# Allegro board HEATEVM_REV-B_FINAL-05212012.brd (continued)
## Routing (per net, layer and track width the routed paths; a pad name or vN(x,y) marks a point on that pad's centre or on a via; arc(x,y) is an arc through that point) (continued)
ADSCLK: length 36.7
  TOP w0.254: v1(261.62,15.88) 261.41,16.08 U4.38
  TOP w0.305: SB31.2 JP16.5
  L5_SIG w0.305: JP16.5 285.31,20.19 265.18,20.19 261.62,16.64 v1(261.62,15.88)
ADSYNC: length 38
  TOP w0.254: v1(258.19,16.38) 258.39,16.58 U4.39
  TOP w0.305: SB33.2 JP16.1
  L5_SIG w0.305: JP16.1 288.8,20.76 288.61,20.95 265.05,20.95 260.48,16.38 v1(258.19,16.38)
AMP_OUT_CH1_P02: length 14
  TOP w0.305: v1(27.3,4.45) 27.43,4.57 U1.6
  BOTTOM w0.305: v1(27.3,4.45) 26.92,4.06 R15.1 R92.2 26.16,6.86 25.91,7.11 C17.2
AMP_OUT_CH2_P02: length 14
  TOP w0.305: U2.6 27.43,13.72 v1(27.3,13.59)
  BOTTOM w0.305: C24.2 25.91,16.26 26.16,16 R94.2 R31.1 26.92,13.21 v1(27.3,13.59)
AMP_OUT_CH3_P02: length 14
  TOP w0.305: v1(27.3,22.73) 27.43,22.86 U3.6
  BOTTOM w0.305: v1(27.3,22.73) 26.92,22.35 R35.1 R97.2 26.16,25.15 25.91,25.4 C32.2
AMP_VCOM_CH5_P02: length 7.8
  TOP w0.635: JP9.1 43.69,2.08 SB5.2 ; U8.2 49.91,18.03
  TOP w0.889: 49.91,18.03 49.15,18.8 v1(47.12,18.8)
  vias: v1(47.12,18.03) v1(47.12,17.27)
AMP_VCOM_CH8_P03: length 7.8
  TOP w0.635: SB6.2 64.26,2.08 JP502.1 ; U14.2 89.53,18.03
  TOP w0.889: v1(86.74,18.8) 88.77,18.8 89.53,18.03
  vias: v1(86.74,18.03) v1(86.74,17.27)
AWD_P05: length 25.5
  TOP w0.254: U19.21 v1(320.68,8.08)
  TOP w0.305: TP2.1 312.55,16.89 v1(309.75,16.89)
  L5_SIG w0.305: v1(320.68,8.08) 319.83,7.24 313.31,7.24 312.17,8.38 312.17,13.21 309.75,15.62 v1(309.75,16.89)
  BOTTOM w0.305: R85.2 v1(320.68,8.08)
BRDGM_P03: length 18.2
  TOP w0.305: U11.5 v1(77.34,18.16)
  L5_SIG w0.305: JP8.2 75.69,19.81 v1(77.34,18.16)
BRDGP_P03: length 19.5
  TOP w0.305: U11.3 v1(78.61,24)
  L5_SIG w0.305: JP8.3 76.96,22.35 v1(78.61,24)
BUF-BRDGM_P03: length 14.1
  TOP w0.305: U11.7 79.88,17.61 79.59,17.91 v1(79.25,17.91) 78.87,17.91 78.61,17.65 U11.6
  L5_SIG w0.305: v1(79.25,17.91) 81.66,20.32 v1(86.87,20.32)
  BOTTOM w0.305: R55.1 v1(86.87,20.32)
BUF-BRDGP_P03: length 12.9
  TOP w0.305: U11.1 81.15,24.51 80.9,24.26 v1(80.52,24.26) 80.18,24.26 79.88,24.55 U11.2
  L5_SIG w0.305: v1(80.52,24.26) 82.93,21.84 v1(86.87,21.84)
  BOTTOM w0.305: R53.2 v1(86.87,21.84)
CANH1_P05: length 10.6
  TOP w0.305: v1(393.19,17.4) 393.32,17.53 U17.7
  BOTTOM w0.305: JP22.1 392.68,25.27 392.94,25.02 R79.2 392.94,18.41 393.19,18.16 v1(393.19,17.4)
CANH2_P05: length 11.3
  TOP w0.305: U16.7 v1(384.18,17.4)
  BOTTOM w0.305: v1(384.18,17.4) 384.18,19.81 382.02,21.97 R78.2 382.02,25.02 381.76,25.27 JP23.1
CANL1_P05: length 10.6
  TOP w0.305: v1(394.72,17.4) 394.72,17.53 394.59,17.65 U17.6
  BOTTOM w0.305: JP22.2 395.22,25.27 394.97,25.02 R79.1 394.97,18.41 394.72,18.16 v1(394.72,17.4)
CANL2_P05: length 11
  TOP w0.305: U16.6 v1(385.44,17.4)
  BOTTOM w0.305: v1(385.44,17.4) 385.44,20.45 384.05,21.84 R78.1 384.05,25.02 384.3,25.27 JP23.2
CANRX_1_P05: length 79.1
  TOP w0.254: U19.49 v1(339.73,11.08)
  TOP w0.305: U17.4 v1(395.86,11.3)
  L4_SIG w0.305: v1(395.86,11.3) 395.86,12.7 393.07,15.49 381.25,15.49 380.87,15.11 368.94,15.11 359.03,25.02 343.66,25.02 340.49,21.84 340.49,13.59 339.73,12.83 v1(339.73,11.08)
CANRX_2_P05: length 75.1
  TOP w0.254: v1(326.16,1.65) 326.16,2.54 326.41,2.79 U19.29
  TOP w0.305: U16.4 v1(386.71,11.3)
  L4_SIG w0.305: v1(326.16,1.65) 326.16,2.82 327.15,3.81 335.41,3.81 337.69,1.52 376.68,1.52 381,5.84 381,10.92 382.27,12.19 385.83,12.19 v1(386.71,11.3)
CANTX_1_P05: length 71.7
  TOP w0.254: U19.50 338.99,11.58 339.22,11.81 v1(340.87,11.81)
  TOP w0.305: 392.05,9.65 v1(392.05,11.3)
  L4_SIG w0.305: v1(340.87,11.81) 341.32,12.26 341.32,20.64 343.15,22.48 358.9,22.48 366.9,14.48 381.76,14.48 382.14,14.86 389.38,14.86 392.05,12.19 v1(392.05,11.3)
CANTX_2_P05: length 68.6
  TOP w0.254: U19.30 v1(326.91,2.29)
  TOP w0.305: 382.9,9.65 v1(382.9,11.3)
  L4_SIG w0.305: v1(382.9,11.3) 382.9,4.06 379.73,0.89 337.19,0.89 336.3,1.78 328.55,1.78 328.04,2.29 v1(326.91,2.29)
CLKDIV_P04: length 18.4
  TOP w0.254: U4.15 v1(252.95,2.41)
  TOP w0.635: SB21.2 262.64,2.08 JP13.1
  BOTTOM w0.305: R62.1 JP13.1 262.64,2.79 261.49,1.65 253.71,1.65 v1(252.95,2.41)
CLKOUT_P05: length 31.7
  TOP w0.362: U19.48 335.53,10.58 v1(334.73,9.78) ; JP1.3 313.94,2.08 SB23.2
  BOTTOM w0.362: v1(334.73,9.78) 334.73,5.42 333.5,4.19 323.34,4.19 322.33,3.17 315.62,3.17 314.99,3.81 JP1.3
D6M_P03: length 10
  TOP w0.305: 83.31,10.29 v1(84.96,10.29)
  L4_SIG w0.305: JP26.5 83.57,8.89 v1(84.96,10.29)
D6P_P03: length 9.1
  TOP w0.305: U12.3 v1(81.53,9.02)
  L4_SIG w0.305: JP26.6 80.31,3.26 80.31,7.79 v1(81.53,9.02)
D7M_P03: length 24.7
  L4_SIG w0.305: JP26.1 93.73,3.98 96.39,6.64 96.39,13.97 102.74,20.32 v1(104.65,20.32)
  BOTTOM w0.305: R52.2 v1(104.65,20.32)
D7P_P03: length 27.3
  L4_SIG w0.305: JP26.2 91.19,4.19 92.84,5.84 92.84,12.06 102.62,21.84 v1(104.65,21.84)
  BOTTOM w0.305: R48.2 v1(104.65,21.84)
D7PDN_P03: length 40.6
  TOP w0.305: C507.1 v1(98.89,22.14) ; v1(104.65,23.37) 106.55,23.37 107.31,24.13 U13.7
  L4_SIG w0.305: JP26.4 86.11,5.08 87.76,6.73 87.76,14.73 95.16,22.14 v1(98.89,22.14)
  BOTTOM w0.305: v1(104.65,23.37) 103.42,22.14 v1(98.89,22.14)
D485_A_P05: length 20.4
  TOP w0.305: U15.6 376.3,17.78 376.43,17.65 v1(376.43,15.88)
  L5_SIG w0.305: JP18.2 367.03,23.75 370.84,23.75 376.43,18.16 v1(376.43,15.88)
D485_B_P05: length 20.8
  TOP w0.305: v1(374.9,15.88) 374.9,17.65 375.03,17.78 U15.7
  L5_SIG w0.305: JP18.1 365.63,22.61 369.44,22.61 374.9,17.14 v1(374.9,15.88)
D-BRDGM_P03: length 6.4
  TOP w0.305: U14.1 v1(87.38,16.25)
  BOTTOM w0.305: v1(87.38,16.25) 88.39,16.25 ; 88.39,16.25 88.14,16.51 R55.2 R56.2 ; 88.39,16.25 C11.1
D-BRDGP_P03: length 6.4
  TOP w0.305: U14.8 v1(87.38,25.91)
  BOTTOM w0.305: R54.2 R53.1 88.14,25.65 88.39,25.91 ; 88.39,25.91 C48.1 ; 88.39,25.91 v1(87.38,25.91)
D-RTDM_P02: length 11.6
  TOP w0.305: R21.1 43.05,18.54 45.34,16.25 v1(47.75,16.25) U8.1
  BOTTOM w0.305: v1(47.75,16.25) 48.58,16.25 C18.1 49.53,16.32 R20.2
D-RTDP_P02: length 11.7
  TOP w0.305: U8.8 v1(47.75,25.91) 45.34,25.91 43.05,23.62 R18.1
  BOTTOM w0.305: R19.2 49.53,25.91 C20.1 48.52,25.91 v1(47.75,25.91)
DIN: length 48
  TOP w0.254: v1(254.25,5.84) 253.95,5.54 U4.17
  TOP w0.305: SB34.2 JP16.7
  L4_SIG w0.305: v1(254.25,5.84) 255.02,6.6 257.43,6.6 258.7,5.33 264.54,5.33 265.81,4.06 285.62,4.06 287.27,5.71 287.27,10.6 JP16.7
DOUT1: length 41.3
  TOP w0.254: U4.25 v1(261.62,9.58)
  TOP w0.305: SB35.2 JP16.9
  L5_SIG w0.305: JP16.9 285.96,10.6 284.93,9.58 ; 284.93,9.58 286.13,8.38 286.13,3.68 JP7.1 ; 284.93,9.58 284.48,10.03 262.07,10.03 v1(261.62,9.58)
DOUT2_P04: length 36.1
  TOP w0.254: U4.24 v1(258.19,9.08)
  L5_SIG w0.305: v1(258.19,9.08) 259.59,9.08 259.91,8.76 262,8.76 262.51,9.27 283.97,9.27 285.12,8.13 285.12,5.21 JP7.2
DOUT3_P04: length 32.6
  TOP w0.254: U4.23 261.29,8.58 261.62,8.26 v1(261.62,8)
  L5_SIG w0.305: v1(261.62,8) 262.51,8 263.14,8.64 282.83,8.64 284.23,7.24 284.23,5.84 282.83,4.45 281.81,4.45 JP7.3
DOUT4_P04: length 23.2
  TOP w0.254: U4.22 v1(258.19,8.08)
  L5_SIG w0.305: JP7.4 273.18,6.73 261.37,6.73 260.02,8.08 v1(258.19,8.08)
DOUT5_P04: length 21.8
  TOP w0.254: U4.21 255.95,5.54 256.26,5.84 v1(256.29,5.84)
  L5_SIG w0.305: JP7.5 271.53,5.84 v1(256.29,5.84)
DOUT6_P04: length 20.2
  TOP w0.254: v1(255.27,5.84) 255.45,5.66 U4.20
  L5_SIG w0.305: v1(255.27,5.84) 256.03,5.08 269.75,5.08 JP7.6
DOUT7_P04: length 17.4
  TOP w0.254: U4.19 254.95,2.73 v1(255.27,2.41)
  L5_SIG w0.305: JP7.7 268.48,3.81 265.94,3.81 264.54,2.41 v1(255.27,2.41)
DOUT8_P04: length 15.7
  TOP w0.254: v1(254.13,2.41) 254.45,2.74 U4.18
  L5_SIG w0.305: JP7.8 266.19,1.52 255.02,1.52 v1(254.13,2.41)
FLCLK_P05: length 91.5
  TOP w0.362: SB23.1 311.4,2.08 ; 311.4,2.08 JP1.2 ; 311.4,2.08 SB24.1 ; v1(392.05,4.95) 392.21,5.12 U18.5
  BOTTOM w0.362: JP1.2 313.06,2.16 322.58,2.16 323.72,3.3 335.79,3.3 337.95,1.14 386.84,1.14 390.65,4.95 v1(392.05,4.95)
FORMAT0_P04: length 24.9
  TOP w0.254: U4.42 v1(259.91,19.05)
  TOP w0.305: SB17.2 JP10.1
  L5_SIG w0.305: JP10.1 275.63,23.16 263,23.16 259.91,20.07 v1(259.91,19.05)
  BOTTOM w0.305: R5.2 JP10.1
FORMAT1_P04: length 28.4
  TOP w0.254: U4.41 261.24,17.58 261.62,17.96 261.62,18.41 v1(260.99,19.05)
  TOP w0.305: SB18.2 JP10.3
  L5_SIG w0.305: v1(260.99,19.05) 260.99,19.68 263.78,22.48 277.5,22.48 JP10.3
  BOTTOM w0.305: R4.2 JP10.3
FORMAT2_P04: length 32.6
  TOP w0.254: U4.40 258.64,17.08 v1(258.19,17.53)
  TOP w0.305: SB19.2 JP10.5
  L5_SIG w0.305: v1(258.19,17.53) 260.6,17.53 264.8,21.72 279.27,21.72 JP10.5
  BOTTOM w0.305: R3.2 JP10.5
GPIOA0_P05: length 4.6
  TOP w0.254: U19.83 323.41,23.8 323.34,23.88 v1(323.34,24)
  L4_SIG w0.305: JP14.1 323.34,25.53 v1(323.34,24)
GPIOA1_P05: length 60.6
  TOP w0.254: U19.80 324.91,23.37 324.36,23.92 v1(324.36,24)
  TOP w0.305: SB36.1 286.31,7.38 286.89,6.79 291.08,6.79 JP16.12
  L4_SIG w0.305: JP14.2 324.36,25.53 v1(324.36,24) 324.36,23.37 323.34,22.35 323.34,8.89 320.8,6.35 298.2,6.35 296.48,8.06 JP16.12
GPIOA2_P05: length 5.5
  TOP w0.254: U19.79 v1(325.41,24)
  L4_SIG w0.305: JP14.3 326.94,25.57 326.35,25.57 325.41,24.64 v1(325.41,24)
GPIOA3_P05: length 7.1
  TOP w0.254: v1(326.39,24) 326.39,23.88 325.91,23.4 U19.78
  L4_SIG w0.305: JP14.4 329.5,25.59 328.74,25.59 328.17,25.02 327.15,25.02 326.39,24.26 v1(326.39,24)
GPIOA4_P05: length 7.4
  TOP w0.254: U19.73 v1(328.41,24.26)
  L4_SIG w0.305: JP14.5 331.28,24.83 328.99,24.83 328.87,24.71 328.86,24.71 v1(328.41,24.26)
GPIOA5_P05: length 12.4
  TOP w0.254: U19.58 335.47,15.58 335.03,16.03 v1(335.03,17.27)
  L4_SIG w0.305: JP14.6 335.28,19.05 335.03,18.8 v1(335.03,17.27)
GPIOA6_P05: length 20.6
  TOP w0.254: U19.46 v1(338.96,9.58)
  L4_SIG w0.305: v1(338.96,9.58) 338.33,9.58 336.68,11.23 336.68,24 337.82,25.15 JP14.7
GPIOA7_P05: length 23.6
  TOP w0.254: U19.47 338.33,10.08 338.6,10.35 340.55,10.35 v1(340.87,10.67)
  L4_SIG w0.305: v1(340.87,10.67) 340.42,10.22 339.41,10.22 337.95,11.68 337.95,16.89 338.71,17.65 338.71,23.62 340.36,25.27 JP14.8
HET2_P05: length 43.8
  TOP w0.254: v1(332.23,2.41) 332.41,2.59 U19.41
  L5_SIG w0.305: v1(332.23,2.41) 332.23,3.17 330.96,4.45 323.98,4.45 321.69,6.73 321.69,9.27 319.91,11.05 314.45,11.05 313.12,12.38 313.12,13.4 310.83,15.68 310.83,18.99 306.07,23.75 JP15.3
HET3_P05: length 45.8
  TOP w0.254: U19.38 330.91,2.72 v1(331.22,2.41)
  L5_SIG w0.305: v1(331.22,2.41) 331.22,3.05 330.45,3.81 321.44,3.81 318.64,6.6 312.93,6.6 311.4,8.13 311.4,12.95 308.86,15.49 308.86,19.43 303.53,24.77 JP15.2
HET4_P05: length 46
  TOP w0.254: U19.37 330.41,2.63 v1(330.2,2.41)
  L5_SIG w0.305: JP15.1 300.99,25.15 308.1,18.03 308.1,15.11 310.64,12.57 310.64,7.87 312.55,5.97 316.87,5.97 319.66,3.17 329.44,3.17 v1(330.2,2.41)
HET6_P05: length 14
  TOP w0.254: U19.6 317.26,15.58 317.09,15.75 v1(316.48,15.75)
  L5_SIG w0.305: JP15.8 318.77,18.03 v1(316.48,15.75)
HET8_P05: length 15
  TOP w0.254: v1(316.48,14.73) 317.09,14.73 317.44,15.08 U19.7
  L5_SIG w0.305: JP15.7 316.23,18.16 315.6,17.53 315.6,15.24 316.1,14.73 v1(316.48,14.73)
HOLDN_P05: length 4.4
  TOP w0.305: v1(397.38,2.29) 396.95,2.72 U18.2
  BOTTOM w0.305: v1(397.38,2.29) 396.62,1.52 R99.1
I-ADC_CH5M_P02: length 6.7
  TOP w0.305: v1(53.34,16.26) 53.21,16.26 53.21,16.25 U8.4
  BOTTOM w0.305: R501.2 R20.1 51.56,16.32 C18.2 52.51,16.26 v1(53.34,16.26)
I-ADC_CH5P_P02: length 6.8
  TOP w0.305: v1(53.34,25.91) 53.34,25.91 U8.5
  BOTTOM w0.305: v1(53.34,25.91) 52.58,25.91 C20.2 51.56,25.91 R19.1 R502.2
I-ADC_CH7M_P03: length 4.4
  TOP w0.305: v1(110.74,25.91) U13.5
  BOTTOM w0.305: v1(110.74,25.91) 109.73,25.91 ; 109.73,25.91 C56.2 ; 109.73,25.91 109.98,25.65 R49.2
I-ADC_CH7P_P03: length 4.4
  TOP w0.305: U13.4 v1(110.74,16.25)
  BOTTOM w0.305: 109.73,16.25 109.98,16.51 R50.2 ; 109.73,16.25 C58.2 ; 109.73,16.25 v1(110.74,16.25)
I-ADC_CH8M_P03: length 4.4
  TOP w0.305: U14.4 v1(92.96,16.25)
  BOTTOM w0.305: 91.95,16.25 92.2,16.51 R58.2 ; 91.95,16.25 v1(92.96,16.25) ; 91.95,16.25 C11.2
I-ADC_CH8P_P03: length 4.4
  TOP w0.305: v1(92.96,25.91) U14.5
  BOTTOM w0.305: 91.95,25.91 C48.2 ; 91.95,25.91 v1(92.96,25.91) ; 91.95,25.91 92.2,25.65 R57.2
I_INM_4_P03: length 27.6
  TOP w0.305: v1(58.29,10.67) R37.2
  L4_SIG w0.305: JP26.7 74.8,6.22 74.8,9.4 72.64,11.56 59.18,11.56 v1(58.29,10.67)
I_INP_1_P02: length 4.1
  BOTTOM w0.305: R30.1 R13.2 C17.1
I_INP_2_P02: length 4.1
  BOTTOM w0.305: R44.1 R29.2 C24.1
I_INP_3_P02: length 4.1
  BOTTOM w0.305: C32.1 R34.2 R46.1
INM_1_P02: length 4.9
  TOP w0.305: U1.2 v1(20.95,5.84)
  BOTTOM w0.305: v1(20.95,5.84) 21.21,6.1 R93.2 R92.1
INM_2_P02: length 4.9
  TOP w0.305: U2.2 v1(20.95,14.99)
  BOTTOM w0.305: v1(20.95,14.99) 21.21,15.24 R95.2 R94.1
INM_3_P02: length 4.9
  TOP w0.305: U3.2 v1(20.95,24.13)
  BOTTOM w0.305: v1(20.95,24.13) 21.21,24.38 R96.2 R97.1
INM_4_P03: length 9.3
  TOP w0.305: R37.1 62.51,10.67 62.89,10.29 v1(66.67,10.29)
  BOTTOM w0.305: v1(66.67,10.29) 67.44,10.29 C45.1 68.58,11.43 R38.1
INM_7_P03: length 6.4
  TOP w0.305: U13.1 v1(105.16,16.25)
  BOTTOM w0.305: 106.17,16.25 C58.1 ; 106.17,16.25 v1(105.16,16.25) ; 106.17,16.25 105.92,16.51 R52.1 R51.2
INP_1_P02: length 6.2
  TOP w0.305: v1(17.53,4.57) U1.3
  BOTTOM w0.305: C37.1 19.15,1.78 18.74,2.19 18.74,2.22 18.03,2.92 R30.2 18.03,4.06 v1(17.53,4.57)
INP_2_P02: length 6.2
  TOP w0.305: v1(17.53,13.72) U2.3
  BOTTOM w0.305: C33.1 19.15,10.92 18.74,11.33 18.74,11.36 18.03,12.06 R44.2 18.03,13.21 v1(17.53,13.72)
INP_3_P02: length 6.2
  TOP w0.305: v1(17.53,22.86) U3.3
  BOTTOM w0.305: C30.1 19.15,20.07 18.74,20.48 18.74,20.5 18.03,21.21 R46.2 18.03,22.35 v1(17.53,22.86)
INP_4_P03: length 9.3
  TOP w0.305: v1(66.67,9.02) U9.3 62.89,9.02 62.51,8.64 R39.2
  BOTTOM w0.305: R40.1 68.58,7.87 C50.1 67.44,9.02 v1(66.67,9.02)
INP_7_P03: length 6.4
  TOP w0.305: U13.8 v1(105.16,25.91)
  BOTTOM w0.305: 106.17,25.91 105.92,25.65 R48.1 R47.2 ; 106.17,25.91 C56.1 ; 106.17,25.91 v1(105.16,25.91)
INT_2P5VREF_P02: length 8
  TOP w0.635: SB3.2 132.59,2.08 JP5.1 ; 122.05,13.97 v1(121.28,13.21) ; 122.05,13.97 v1(122.81,13.21) ; 122.05,13.97 U6.6
IO_CTRL_P05: length 30.9
  TOP w0.305: U15.2 v1(375.03,11.94) 375.79,11.94 376.3,11.43 U15.3
  BOTTOM w0.305: JP17.2 374.9,27.3 376.56,27.3 380.24,23.62 R64.1 375.92,12.83 v1(375.03,11.94)
ISO_VREF_P02: length 7.1
  TOP w0.305: U7.7 49.02,11.05 48.39,10.41 v1(48.39,9.78) U7.6
  BOTTOM w0.305: R25.2 v1(48.39,9.78)
JTCK_P05: length 48.3
  TOP w0.254: U19.45 338.33,9.08 338.52,8.89 339.62,8.89 339.75,8.76 v1(340.36,8.76)
  TOP w0.635: SB25.1 340.87,2.08 JP21.2
  L4_SIG w0.305: v1(340.36,8.76) 341.63,8.76 343.03,10.16 343.03,15.24 343.92,16.13 JP20.9
  BOTTOM w0.305: JP21.2 341.76,4.7 351.03,4.7 351.28,4.95 R65.2 353.06,5.97 354.33,7.24 354.33,11.68 353.69,12.32 350.65,12.32 348.11,14.86 346.2,14.86 JP20.9
JTDI_P05: length 36.1
  TOP w0.254: v1(338.84,7.49) 338.71,7.62 338.28,7.62 337.82,8.08 U19.43
  L4_SIG w0.305: 344.93,21.21 342.26,18.54 342.26,10.67 341.12,9.53 339.85,9.53 338.84,8.51 v1(338.84,7.49)
  L5_SIG w0.305: 344.93,21.21 345.95,22.23 351.92,22.23 354.46,19.68 354.46,17.53 JP19.3
  BOTTOM w0.305: R68.1 JP19.3
JTDO_P05: length 18.9
  TOP w0.254: U19.44 338.2,8.58 338.35,8.43 339.29,8.43 v1(339.73,8)
  L4_SIG w0.305: v1(339.73,8) 342.14,8 344.21,10.08 344.21,10.33 346.2,12.32 351.79,12.32 JP19.7
JTMS2_P05: length 4.3
  TOP w0.254: U19.10 320.41,13.58 v1(320.68,13.84)
  BOTTOM w0.305: v1(320.68,13.84) 319.53,14.99 319.53,15.88
JTMS_P05: length 39.5
  TOP w0.254: v1(320.68,12.83) 320.55,12.83 320.29,13.08 U19.11
  L5_SIG w0.305: v1(320.68,12.83) 326.14,18.29 339.09,18.29 339.47,18.67 JP20.7 346.2,19.94 351.79,19.94 JP19.1
  BOTTOM w0.305: R67.1 JP19.1
JTRSTN_P05: length 46.6
  TOP w0.254: U19.84 322.91,22.99 322.2,23.7 v1(322.2,24)
  L5_SIG w0.305: v1(322.2,24) 322.2,24.38 322.83,25.02 343.66,25.02 344.93,23.75 346.46,25.27 350.77,25.27 355.6,20.45 JP19.2
  BOTTOM w0.305: JP19.2 353.06,21.21 R69.2
LBK1_P05: length 10.4
  TOP w0.305: v1(395.73,17.4) 395.86,17.53 U17.5 ; v1(398.65,19.3) TP3.1
  L4_SIG w0.305: v1(395.73,17.4) 395.73,18.03 397,19.3 v1(398.65,19.3)
  BOTTOM w0.305: R72.2 395.86,17.27 v1(395.73,17.4)
LBK2_P05: length 20.8
  TOP w0.305: U16.5 v1(386.71,17.4) ; TP4.1 v1(398.65,14.48)
  L4_SIG w0.305: v1(386.71,17.4) 387.86,18.54 393.32,18.54 393.95,17.91 393.95,17.02 395.35,15.62 397.51,15.62 v1(398.65,14.48)
  BOTTOM w0.305: v1(386.71,17.4) R74.2
MCS_P05: length 25.6
  TOP w0.305: SB26.2 JP27.2 ; v1(376.3,3.52) U18.12
  L5_SIG w0.305: JP27.2 369.95,13.59 376.3,7.24 v1(376.3,3.52)
MODE0_P04: length 47.1
  TOP w0.254: v1(256.79,19.18) 255.45,20.52 U4.44
  TOP w0.305: JP11.1 SB20.2
  L5_SIG w0.305: JP11.1 225.81,22.61 231.65,22.61 236.6,27.56 250.44,27.56 256.79,21.21 v1(256.79,19.18)
  BOTTOM w0.305: R2.2 JP11.1
MODE1_P04: length 46.4
  TOP w0.254: v1(257.56,18.54) 257.56,19.3 255.95,20.91 U4.43
  TOP w0.305: JP11.3 SB22.2
  L5_SIG w0.305: JP11.3 231.39,28.19 250.82,28.19 257.56,21.46 v1(257.56,18.54)
  BOTTOM w0.305: R7.2 JP11.3
MSCLK_P05: length 20.4
  TOP w0.305: U18.9 v1(375.54,5.92) ; SB30.2 363.73,3.43
  L5_SIG w0.305: v1(375.54,5.92) 375.54,3.68 374.9,3.05 367.16,3.05 366.78,3.43 363.73,3.43
MSI_P05: length 16.4
  TOP w0.305: SB28.2 JP27.6 ; U18.10 v1(374.14,5.12)
  L5_SIG w0.305: v1(374.14,5.12) 372.83,5.12 369.44,8.51 JP27.6
MSO_P05: length 17.2
  TOP w0.305: U18.11 v1(374.9,4.32) ; SB29.2 JP27.8
  L5_SIG w0.305: JP27.8 369.32,5.97 370.97,4.32 v1(374.9,4.32)
N66709_P04: length 7.3
  TOP w0.254: U4.73 243.34,13.58 243.52,13.4
  TOP w0.508: 244.73,12.95 244.28,13.4 243.52,13.4
  TOP w0.635: U5.3 v1(101.22,9.02) v1(102.11,9.02)
  TOP w0.762: v1(244.73,11.18) v1(244.73,11.94) v1(244.73,12.7) 244.73,12.95
N82092_P04: length 32.4
  TOP w0.254: U4.13 251.95,5.7 v1(252.22,5.97) 252.45,5.74 U4.14
  TOP w0.305: TP5.1 v1(272.92,12.19)
  L5_SIG w0.305: v1(272.92,12.19) 272.47,12.64 262.45,12.64 261.55,11.74 257.36,11.74 252.22,6.6 v1(252.22,5.97)
  BOTTOM w0.305: v1(252.22,5.97) 252.22,5.33 252.73,4.83 R6.1
OSCCLK_P05: length 49.2
  TOP w0.362: v1(309.75,21.46) 312.55,21.46 TP1.1 ; JP1.1 308.86,2.08 SB24.2 ; U19.19 v1(320.68,9.08)
  BOTTOM w0.362: JP1.1 306.58,6.1 OSC1.5 308.36,10.41 308.36,20.07 v1(309.75,21.46) 316.61,21.46 318.26,19.81 318.26,10.79 319.98,9.08 v1(320.68,9.08)
OUT_CH6_P03: length 7.8
  TOP w0.305: v1(86.61,8.26) 87.38,9.02 U12.6
  BOTTOM w0.305: R45.1 v1(86.61,8.26)
OUTB_FB_P02: length 9.9
  TOP w0.305: v1(43.56,9.78) U7.3 39.78,9.78 39.14,9.14 R26.2 38.35,7.94 38.86,7.43 C22.1
  BOTTOM w0.305: v1(43.56,9.78) R25.1
PDN_P02: length 10.6
  TOP w0.635: R500.2 55.24,24 v1(54.23,24) 50.29,24 49.91,24.38 U8.7
  BOTTOM w0.635: v1(54.23,24) 55.79,25.57 C505.1
PORSTN: length 181.1
  TOP w0.254: v1(331.22,19.43) 331.22,20.4 330.91,20.7 U19.68
  TOP w0.305: v1(299.85,21.46) 302.64,21.46 TP9.1
  BOTTOM w0.305: JP2.7 172.97,24.64 185.8,24.64 189.23,21.21 199.26,21.21 201.29,19.18 229.74,19.18 232.28,21.72 232.28,23.88 236.09,27.69 259.08,27.69 260.99,25.78 272.8,25.78 274.57,27.56 282.83,27.56 287.4,22.99 292.23,22.99 293.75,21.46 v1(299.85,21.46) 301.12,22.73 328.8,22.73 331.22,20.32 v1(331.22,19.43)
PWRDNN_1_P04: length 60.4
  TOP w0.254: U4.52 251.45,20.18 250.75,19.48 250.75,19.35 v1(250.32,18.92)
  TOP w0.305: JP12.1 SB9.2
  L5_SIG w0.305: v1(250.32,18.92) 249.3,18.92 248.41,19.81 235.97,19.81 232.54,16.38 209.68,16.38 203.2,22.86 JP12.1
  BOTTOM w0.305: R8.2 JP12.1
PWRDNN_2_P04: length 59.5
  TOP w0.254: U4.51 251.95,20.05 251.21,19.3 v1(251.21,18.54)
  TOP w0.305: JP12.3 SB10.2
  L5_SIG w0.305: v1(251.21,18.54) 251.21,19.18 250.7,19.68 249.68,19.68 248.92,20.45 235.71,20.45 232.28,17.02 211.58,17.02 205.74,22.86 JP12.3
  BOTTOM w0.305: R1.2 JP12.3
PWRDNN_3_P04: length 57
  TOP w0.254: v1(251.97,19.18) 251.97,19.43 252.45,19.91 U4.50
  TOP w0.305: JP12.5 SB11.2
  L5_SIG w0.305: v1(251.97,19.18) 251.97,20.32 251.21,21.08 235.46,21.08 232.03,17.65 213.49,17.65 208.28,22.86 JP12.5
  BOTTOM w0.305: R9.2 JP12.5
PWRDNN_4_P04: length 56.4
  TOP w0.254: v1(252.77,18.54) 252.77,19.63 252.95,19.81 U4.49
  TOP w0.305: JP12.7 SB12.2
  L5_SIG w0.305: JP12.7 210.82,22.86 215.39,18.29 231.78,18.29 235.2,21.72 251.33,21.72 252.77,20.28 v1(252.77,18.54)
  BOTTOM w0.305: R10.2 JP12.7
PWRDNN_5_P04: length 54.5
  TOP w0.254: U4.48 253.45,19.34 v1(253.62,19.18)
  TOP w0.305: JP12.9 SB13.2
  L5_SIG w0.305: JP12.9 213.36,22.86 217.3,18.92 231.52,18.92 236.22,23.62 244.22,23.62 245.49,22.35 251.59,22.35 253.62,20.32 v1(253.62,19.18)
  BOTTOM w0.305: R11.2 JP12.9
PWRDNN_6_P04: length 55.1
  TOP w0.254: U4.47 253.95,19.86 254.44,19.37 v1(254.44,18.54)
  TOP w0.305: JP12.11 SB14.2
  L5_SIG w0.305: JP12.11 215.9,22.86 219.2,19.56 231.27,19.56 236.98,25.27 239.52,25.27 240.41,24.38 245.87,24.38 247.27,22.99 251.97,22.99 254.44,20.51 v1(254.44,18.54)
  BOTTOM w0.305: R12.2 JP12.11
PWRDNN_7_P04: length 52.1
  TOP w0.254: U4.46 254.45,20 v1(255.27,19.18)
  TOP w0.305: JP12.13 SB15.2
  L5_SIG w0.305: JP12.13 221.11,21.21 232.03,21.21 236.85,26.04 239.9,26.04 240.92,25.02 243.84,25.02 245.11,26.29 249.68,26.29 255.27,20.7 v1(255.27,19.18)
  BOTTOM w0.305: R60.2 JP12.13
PWRDNN_8_P04: length 51.1
  TOP w0.254: U4.45 254.95,20.38 256.03,19.3 v1(256.03,18.54)
  TOP w0.305: JP12.15 SB16.2
  L5_SIG w0.305: v1(256.03,18.54) 256.03,21.08 250.19,26.92 236.85,26.92 231.78,21.84 223.01,21.84 JP12.15
  BOTTOM w0.305: R61.2 JP12.15
REFHI_P05: length 3.1
  TOP w0.254: U19.64 332.91,23.26 v1(333.38,23.72)
  BOTTOM w0.305: R84.2 333.6,23.5 v1(333.38,23.72)
REFLO_P05: length 5.4
  TOP w0.254: U19.65 332.41,23.69 v1(332.36,23.75)
  BOTTOM w0.305: v1(332.36,23.75) 332.36,22.61 333.25,21.72 R83.2
RJTCK_P05: length 30.8
  TOP w0.635: SB25.2 338.33,2.08 JP21.1
  BOTTOM w0.254: R66.2 351.28,7.49 351.03,7.24 341.76,7.24 JP21.1
  BOTTOM w0.305: R66.2 JP19.9 353.06,9.14 352.3,9.91 351.28,9.91 348.87,12.32 346.2,12.32 344.93,13.59
RSTN_P05: length 91.7
  TOP w0.254: U19.69 v1(330.41,19.94)
  TOP w0.305: U18.3 v1(397.38,3.52)
  L4_SIG w0.305: v1(330.41,19.94) 330.41,18.71 332.62,16.5 334.65,16.5 335.79,15.37 335.79,8.89 337.82,6.86 342.26,6.86 343.92,8.51 JP20.15 346.2,9.78 356.49,9.78 359.03,12.32 365.76,12.32 367.28,13.84 381.63,13.84 382.27,13.21 387.22,13.21 391.41,9.02 393.95,9.02 395.73,7.24 395.73,4.45 396.66,3.52 v1(397.38,3.52)
  BOTTOM w0.305: R81.1 397.35,3.56 v1(397.38,3.52)
RTDM_P02: length 12
  TOP w0.305: v1(38.35,13.08) R24.2 39.14,11.68 39.78,11.05 U7.2
  TOP w0.635: JP4.1 35.36,17.27 SB2.2
  L5_SIG w0.305: JP4.1 38.35,16 v1(38.35,13.08)
RTDP_P02: length 17.9
  TOP w0.305: 41.15,12.32 39.79,12.32 39.5,12.61 v1(39.5,13.08)
  TOP w0.635: JP4.4 35.36,24.89 SB1.2
  L5_SIG w0.305: JP4.4 38.99,22.99 38.99,13.59 v1(39.5,13.08)
S-RTDM_P02: length 8.1
  TOP w0.305: JP4.2 37.91,20.64 RTD.1 R21.2
  TOP w0.635: SB2.1 35.36,19.81 JP4.2
S-RTDP_P02: length 8.1
  TOP w0.305: JP4.3 37.91,21.53 RTD.2 R18.2
  TOP w0.635: SB1.1 35.36,22.35 JP4.3
SCICLK3_P05: length 21.1
  TOP w0.254: v1(316.1,11.81) 316.71,11.81 316.94,11.58 U19.14
  L5_SIG w0.305: v1(316.1,11.81) 315.2,11.81 314.2,12.82 314.2,13.46 312.04,15.62 312.04,21.08 308.61,24.51 JP15.4
SCICLK_1_P05: length 81.8
  TOP w0.254: U19.26 324.91,2.79 325.18,2.52 v1(325.18,1.65)
  L5_SIG w0.305: JP17.3 375.92,23.11 379.35,19.68 379.35,4.57 376.17,1.4 344.04,1.4 343.54,1.91 335.15,1.91 334.01,0.76 326.07,0.76 v1(325.18,1.65)
SCIRX3_P05: length 19
  TOP w0.254: U19.13 317.23,12.08 v1(316.74,12.57)
  L5_SIG w0.305: v1(316.74,12.57) 315.84,12.57 315.21,13.2 315.21,13.59 312.99,15.81 312.99,22.29 311.15,24.13 JP15.5
SCIRX_1_P05: length 61.5
  TOP w0.254: U19.25 v1(324.41,2.29)
  TOP w0.305: U15.1 v1(373.76,11.3)
  L4_SIG w0.305: v1(373.76,11.3) 372.75,10.29 372.75,5.59 369.32,2.16 338.2,2.16 336.04,4.32 325.75,4.32 324.41,2.98 v1(324.41,2.29)
SCITX3_P05: length 17.2
  TOP w0.254: U19.12 317.63,12.58 316.87,13.34 v1(315.98,13.34)
  L5_SIG w0.305: v1(315.98,13.34) 315.98,13.97 313.69,16.26 JP15.6
SCITX_1_P05: length 90.1
  TOP w0.254: U19.24 323.91,2.79 323.66,2.54 v1(323.66,1.65)
  TOP w0.305: 377.57,9.65 v1(377.57,11.3) ; TP6.1 312.55,12.32 v1(309.75,12.32)
  L4_SIG w0.305: v1(323.66,1.65) 323.66,3.24 325.37,4.95 342.52,4.95 342.77,4.7 365.63,4.7 368.68,7.75 368.68,9.27 372.11,12.7 376.81,12.7 377.57,11.94 v1(377.57,11.3)
  L5_SIG w0.305: v1(309.75,12.32) 309.75,7.62 312.04,5.33 315.98,5.33 319.66,1.65 v1(323.66,1.65)
SPI2_CLK_P05: length 44.8
  TOP w0.254: U19.31 327.41,2.79 327.68,2.52 v1(327.68,1.65)
  TOP w0.305: 361.19,3.43 362.46,4.7 366.39,4.7 366.98,4.11 SB30.1
  L5_SIG w0.305: v1(327.68,1.65) 328.32,1.65 328.7,1.27 333.5,1.27 334.77,2.54 343.92,2.54 344.42,2.03 358.14,2.03 359.54,3.43 361.19,3.43
SPI2_ENAN_P05: length 44.8
  TOP w0.254: U19.34 328.91,5.46 329.17,5.72 v1(329.17,6.6)
  TOP w0.305: SB27.1 366.98,11.73 366.39,12.32 362.46,12.32 JP27.3
  L4_SIG w0.305: v1(329.17,6.6) 330.06,7.49 335.41,7.49 336.8,6.1 343.03,6.1 344.3,7.37 357.5,7.37 JP27.3
SPI2_MISO_P05: length 45.8
  TOP w0.254: v1(327.64,6.6) 327.64,5.73 327.91,5.46 U19.32
  TOP w0.305: SB29.1 366.98,6.65 366.39,7.24 362.46,7.24 JP27.7
  L5_SIG w0.305: JP27.7 360.05,7.11 343.41,7.11 342.26,5.97 334.77,5.97 333.38,7.37 330.83,7.37 329.31,5.84 328.41,5.84 v1(327.64,6.6)
SPI2_MOSI_P05: length 46.1
  TOP w0.254: U19.33 v1(328.41,7.62)
  TOP w0.305: SB28.1 366.98,9.19 366.39,9.78 362.46,9.78 JP27.5
  L5_SIG w0.305: v1(328.41,7.62) 328.86,8.07 334.32,8.07 335.79,6.6 341.25,6.6 344.42,9.78 359.92,9.78 JP27.5
SPI2_SCSN_P05: length 53.8
  TOP w0.254: v1(329.18,2.41) 329.41,2.64 U19.35
  TOP w0.305: SB26.1 366.98,14.4 366.52,14.86 362.46,14.86 JP27.1
  L5_SIG w0.305: JP27.1 362.33,12.45 362.33,5.33 361.7,4.7 342.77,4.7 342.26,5.21 335.15,5.21 333.5,3.56 333.5,2.41 332.87,1.78 329.82,1.78 v1(329.18,2.41)
SPI_CLK1_P05: length 41.8
  TOP w0.254: U19.3 v1(322.07,17.08)
  TOP w0.305: SB31.1 286.31,15 286.89,14.41 291.08,14.41 JP16.6
  L4_SIG w0.305: v1(322.07,17.08) 321.44,17.08 321.31,17.21 311.47,17.21 308.99,14.73 293.31,14.73 JP16.6
SPI_ENAN1_P05: length 39.1
  TOP w0.254: v1(321.31,17.91) 320.98,17.58 U19.2
  TOP w0.305: SB32.1 286.31,17.54 286.89,16.95 291.08,16.95 JP16.4
  L4_SIG w0.305: v1(321.31,17.91) 296.42,17.91 296.1,18.22 JP16.4
SPI_MISO1_P05: length 42.6
  TOP w0.254: v1(322.07,15.42) 320.96,15.42 320.29,16.08 U19.5
  TOP w0.305: JP16.10 291.08,9.33 286.89,9.33 286.31,9.92 SB35.1
  L4_SIG w0.305: v1(322.07,15.42) 320.98,15.42 316.36,10.79 293.56,10.79 293.37,10.6 JP16.10
SPI_MOSI1_P05: length 40.4
  TOP w0.254: U19.4 320.99,16.58 v1(321.31,16.26)
  TOP w0.305: SB34.1 286.31,12.46 286.89,11.87 291.08,11.87 JP16.8
  L4_SIG w0.305: v1(321.31,16.26) 320.68,16.26 320.42,16.51 312.29,16.51 308.93,13.14 JP16.8
SPI_SCSN1_P05: length 41.5
  TOP w0.254: v1(322.07,18.8) 321.01,18.8 320.29,18.08 U19.1
  TOP w0.305: JP16.2 291.08,19.49 286.89,19.49 286.31,20.08 SB33.1
  L4_SIG w0.305: JP16.2 295.59,20.76 297.69,18.67 321.31,18.67 321.44,18.8 v1(322.07,18.8)
SRC_EXT_VCOM_P03:
  vias: v1(96.01,3.19) v1(96.01,2.43) v1(96.77,3.19) v1(96.77,2.43)
STAT3_P05: length 75.6
  TOP w0.254: v1(335.92,1.02) 334.64,1.02 332.91,2.75 U19.42
  TOP w0.305: 392.05,19.31 392.05,17.53 v1(392.18,17.4)
  L5_SIG w0.305: v1(392.18,17.4) 391.29,16.51 391.29,9.91 382.14,0.76 337.31,0.76 337.06,1.02 v1(335.92,1.02)
  BOTTOM w0.305: v1(392.18,17.4) 392.05,17.27 R63.2
SYNCN: length 53
  TOP w0.254: v1(253.24,5.84) 253.45,5.63 U4.16
  TOP w0.305: SB32.2 JP16.3
  L4_SIG w0.305: JP16.3 286.45,14.86 286.45,6.67 284.48,4.7 266.06,4.7 264.73,6.03 259.27,6.03 258.06,7.24 254.63,7.24 v1(253.24,5.84)
TEST_P05: length 9.6
  TOP w0.254: v1(329.44,24.13) 329.31,24.13 328.91,23.73 U19.72
  BOTTOM w0.305: R70.2 332.87,19.94 329.44,23.37 v1(329.44,24.13)
TRIMER_P02: length 1.8
  TOP w0.889: C5.1 C27.2
  vias: v1(119.76,21.97) v1(120.4,21.97) v1(121.03,21.97) v1(121.67,21.97)
U12_RG1_P03: length 3.8
  TOP w0.305: v1(84.96,11.56) U12.1
  BOTTOM w0.305: R42.1 v1(84.96,11.56)
U12_RG2_P03: length 3.8
  TOP w0.305: v1(91.31,11.56) U12.8
  BOTTOM w0.305: R42.2 v1(91.31,11.56)
VBRDGP_P03: length 19.7
  TOP w0.305: U10.6 69.98,24.51 v1(70.48,24) ; U10.2 v1(68.71,17.91)
  L4_SIG w0.305: v1(68.71,17.91) 70.48,19.68 v1(70.48,24) 69.6,24.89 JP8.4
VCOM: length 9.8
  TOP w0.635: SB6.1 61.72,2.08 JP502.2 ; JP9.2 46.23,2.08 SB5.1 ; SB8.2 104.65,2.08 ; 104.65,2.08 JP500.2 ; 104.65,2.08 SB7.2
  vias: v1(50.16,4.7) v1(50.16,3.81) v1(50.16,2.92) v1(57.78,4.7) v1(57.78,3.81) v1(57.78,2.92) v1(99.19,2.41) v1(99.95,2.41) v1(100.71,2.41)
VREF: length 40.7
  TOP w0.254: U4.81 240.47,9.58 v1(240.16,9.27) ; U4.74 240.54,13.08 240.41,13.21 ; U4.65 243.21,17.58 243.62,18
  TOP w0.635: v1(69.98,14.61) U10.3 v1(69.98,17.91) ; R39.1 v1(58.29,8.64) ; v1(8.13,20.83) R14.2 v1(6.99,19.68) ; 243.62,18 243.91,18.29 246.13,18.29 ; v1(94.61,7.75) v1(91.31,7.75) ; 130.05,2.08 JP5.2 ; 130.05,2.08 SB3.1 ; 130.05,2.08 SB4.1 ; C501.1 U7.5 ; C10.1 240.41,13.21 ; SB8.1 102.11,2.08 JP500.3
  BOTTOM w0.508: C526.2 241.05,10.15 241.05,9.53 240.79,9.27 v1(240.16,9.27) 239.01,9.27 238.38,9.91 238.38,11.56 v1(237.36,12.57)
  BOTTOM w0.635: R27.2 v1(11.94,17.53) ; R32.2 v1(11.94,26.67) ; R16.2 v1(11.94,8.38)
  vias: v1(54.48,9.4) v1(54.48,8.51) v1(54.48,7.62) v1(126.62,8.26) v1(127.51,8.26) v1(128.4,8.26) v1(129.67,9.14) v1(130.43,9.14) v1(131.19,9.14) v1(131.95,9.14) v1(132.46,8.38) v1(132.46,7.62) v1(132.46,6.86) v1(237.36,13.84) v1(237.36,13.21) v1(246.76,18.67) v1(246.76,17.78) v1(246.76,16.89)
WPN_P05: length 13.7
  TOP w0.305: U18.4 396.88,4.32 v1(397.38,4.83) ; TP7.1 v1(398.65,9.91)
  L4_SIG w0.305: v1(398.65,9.91) 398.65,9.27 399.16,8.76 399.16,5.97 398.02,4.83 v1(397.38,4.83)
  BOTTOM w0.305: v1(397.38,4.83) 396.62,5.59 R98.1
X-AXIS_P02: length 17.6
  BOTTOM w0.305: JP3.3 3,8.85 8.17,8.85 11.94,5.08 R13.1 ; R13.1 R16.1 ; R13.1 R17.2
XT_VOUT_P02: length 2.9
  TOP w0.635: SB4.2 127.51,2.08 JP5.3
Y-AXIS_P02: length 16.2
  BOTTOM w0.305: R29.1 R28.2 ; R29.1 11.68,14.22 10.67,13.21 JP3.5 ; R29.1 R27.1
Z-AXIS_P02: length 17.9
  BOTTOM w0.305: JP3.7 6.86,18.29 11.94,23.37 R34.1 ; R34.1 R33.2 ; R34.1 R32.1

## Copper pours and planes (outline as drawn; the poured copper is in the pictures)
GND on TOP (solid shape): 258.7,10.16 258.7,10.03 258.39,9.73 256.97,9.73 256.77,9.93 256.77,10.24 256.97,10.44 258.42,10.44
GND on BOTTOM (solid shape): 53.34,2.29 51.05,2.29 51.05,5.33 53.34,5.33
GND on BOTTOM (solid shape): 56.9,2.29 54.61,2.29 54.61,5.33 56.9,5.33
GND on BOTTOM (solid shape): 302.64,14.99 300.74,14.99 300.74,17.53 302.64,17.53
GND on TOP: 57.28,11.56 57.28,13.08 56.39,13.08 55.88,13.59 55.37,13.59 55.37,11.05 55.88,11.05 56.39,11.56
GND on TOP: 30.73,3.56 30.73,4.06 33.27,4.06 33.27,3.56 32.77,3.05 32.77,2.16 31.24,2.16 31.24,3.05
GND on TOP: 111.25,9.65 111.25,10.16 113.79,10.16 113.79,9.65 113.28,9.14 113.28,8.26 111.76,8.26 111.76,9.14
GND on TOP: 266.57,10.54 266.57,12.06 265.43,12.06 265.18,12.32 264.67,12.32 264.67,10.29 265.18,10.29 265.43,10.54
GND on TOP: 234.57,13.97 234.57,12.45 235.71,12.45 235.97,12.19 236.47,12.19 236.47,14.22 235.97,14.22 235.71,13.97
GND on TOP: 30.73,12.7 30.73,13.21 33.27,13.21 33.27,12.7 32.77,12.19 32.77,11.3 31.24,11.3 31.24,12.19
GND on TOP: 57.28,7.75 57.28,9.27 56.39,9.27 55.88,9.78 55.37,9.78 55.37,7.24 55.88,7.24 56.39,7.75
GND on TOP: 85.98,18.03 85.98,18.54 85.47,19.05 85.47,19.94 83.95,19.94 83.95,19.05 83.44,18.54 83.44,18.03
GND on TOP: 33.27,22.35 30.73,22.35 30.73,21.84 31.24,21.34 31.24,20.45 32.77,20.45 32.77,21.34 33.27,21.84
GND on TOP: 94.23,17.02 94.23,17.53 96.77,17.53 96.77,17.02 96.27,16.51 96.27,15.62 94.74,15.62 94.74,16.51
GND on TOP: 54.61,17.02 54.61,17.53 57.15,17.53 57.15,17.02 56.64,16.51 56.64,15.62 55.12,15.62 55.12,16.51
GND on TOP: 109.35,3.56 109.35,4.06 111.89,4.06 111.89,3.56 111.38,3.05 111.38,2.16 109.86,2.16 109.86,3.05
GND on TOP: 126.75,21.97 126.75,22.48 129.29,22.48 129.29,21.97 128.78,21.46 128.78,20.57 127.25,20.57 127.25,21.46
GND on TOP: 234.57,10.67 234.57,9.14 235.71,9.14 235.97,8.89 236.47,8.89 236.47,10.92 235.97,10.92 235.71,10.67
GND on TOP: 128.78,9.65 128.78,9.14 126.24,9.14 126.24,9.65 126.75,10.16 126.75,11.05 128.27,11.05 128.27,10.16
GND on TOP: 266.57,13.46 266.57,14.99 265.43,14.99 265.18,15.24 264.67,15.24 264.67,13.21 265.18,13.21 265.43,13.46
GND on TOP: 76.2,8 76.2,8.51 78.74,8.51 78.74,8 78.23,7.49 78.23,6.6 76.71,6.6 76.71,7.49
GND on TOP: 234.57,17.02 234.57,15.49 235.71,15.49 235.97,15.24 236.47,15.24 236.47,17.27 235.97,17.27 235.71,17.02
GND on BOTTOM: 331.6,16.51 331.6,15.37 332.87,15.37 332.87,13.84 331.6,13.84 331.6,12.32 332.87,12.32 332.87,10.79 331.6,10.79 331.6,9.65 332.74,9.65 332.74,8.13 331.22,8.13 331.22,9.4 326.64,9.4 326.64,8.13 325.12,8.13 325.12,9.4 324.49,9.4 324.49,10.54 323.21,10.54 323.21,12.06 324.49,12.06 324.49,16.51 324.74,16.51 324.74,18.03 326.26,18.03 326.26,16.51 327.79,16.51 327.79,18.03 329.31,18.03 329.31,16.51
GND on BOTTOM: 241.94,12.95 241.94,11.18 244.09,11.18 244.09,12.95
GND on BOTTOM: 312.29,7.75 314.2,7.75 314.2,10.29 312.29,10.29
GND on BOTTOM: 249.56,16.26 249.56,18.54 248.79,18.54 248.28,19.05 247.65,19.05 247.65,16.51 247.78,16.51 247.78,9.91 254.13,9.91 254.13,16.26
GND on BOTTOM: 229.62,26.42 229.62,24.51 231.14,24.51 231.14,26.42
GND on BOTTOM: 199.14,26.42 199.14,24.51 200.66,24.51 200.66,26.42
GND on L2_GND, L7_GND: 0.64,0.64 0.64,28.19 405.76,28.19 405.76,0.64
GND on L3_PWR: 287.15,27.56 287.15,1.27 405.13,1.27 405.13,27.56
0G_REF_VSRC on TOP: 111.89,4.57 111.89,5.08 111.38,5.59 111.38,6.48 109.86,6.48 109.86,5.59 109.35,5.08 109.35,4.57
0G_REF_VSRC on L3_PWR: 1.27,27.56 1.27,1.27 112.52,1.27 112.52,5.46 103.76,5.46 103.76,2.41 95.5,2.41 95.5,6.6 12.19,6.6 5.46,13.34 5.46,27.56
0G_VREF_P04 on L5_SIG: 248.41,10.54 248.41,1.27 106.05,1.27 106.05,12.7 137.54,12.7 137.54,4.19 180.47,4.19 180.47,10.54
1P8VSRC on TOP (solid shape): 375.67,2.29 375.67,2.03 375.29,1.65 370.36,1.65 370.36,2.18 373.91,2.18 374.27,2.54 375.41,2.54
1P8VSRC on TOP: 327.41,19.18 329.56,19.18 329.82,19.43 329.82,19.68 329.56,19.94 329.56,23.11 329.31,23.11 329.31,20.45 329.18,20.32 327.66,20.32 327.53,20.45 327.53,23.11 327.28,23.11 327.28,19.3
1P8VSRC on TOP: 317.88,10.21 320.73,10.21 321.31,10.79 321.31,14.1 320.93,14.48 317.88,14.48 317.88,14.73 321.69,14.73 322.33,14.1 322.33,10.41 321.87,9.96 317.88,9.96
1P8VSRC on TOP: 325.78,3.05 326.03,3.05 326.03,5.74 326.52,6.22 326.9,6.22 327.15,6.48 327.15,6.73 326.9,6.99 324.87,6.99 324.61,6.73 324.61,6.48 324.87,6.22 325.25,6.22 325.78,5.69
1P8VSRC on TOP: 337.95,13.72 337.95,13.46 334.77,13.46 334.64,13.34 334.14,13.34 334.01,13.46 334.01,15.62 334.24,15.85 334.54,15.85 334.77,15.62 334.77,14.22 335.28,13.72
1P8VSRC on BOTTOM: 327.15,5.21 327.15,6.99 324.61,6.99 324.61,5.21
1P8VSRC on BOTTOM: 320.17,10.03 322.07,10.03 322.07,12.57 321.44,12.57 321.06,12.19 320.17,12.19
1P8VSRC on BOTTOM: 335.92,15.88 334.01,15.88 334.01,13.34 335.92,13.34
1P8VSRC on BOTTOM: 327.28,21.08 327.28,19.18 329.82,19.18 329.82,21.08
1P8VSRC on L5_SIG: 172.21,11.18 172.21,27.69 161.93,27.69 161.93,14.1 156.84,14.1 156.84,11.18
1P8VSRC on L6_PWR: 134.24,1.27 134.24,13.59 201.93,13.59 201.93,12.83 233.17,12.83 233.17,13.59 247.65,13.59 247.65,9.78 254.25,9.78 254.25,13.59 309.37,13.59 309.37,7.11 319.66,7.11 319.66,18.41 327.28,18.41 327.28,19.94 329.82,19.94 329.82,16.38 324.61,16.38 324.61,9.78 329.82,9.78 329.82,5.59 335.41,5.59 335.41,13.34 334.01,13.34 334.01,15.75 339.22,15.75 339.22,3.56 395.73,3.56 395.73,8.26 405.13,8.26 405.13,1.27
3P3VSRC on TOP (solid shape): 369.82,4.7 369.82,3.3 370.15,2.97 373.51,2.97 373.51,2.46 369.14,2.46 368.3,3.3 368.3,4.7 368.55,4.95 369.57,4.95
3P3VSRC on BOTTOM (solid shape): 305.05,14.99 303.15,14.99 303.15,17.53 305.05,17.53
3P3VSRC on TOP: 324.49,19.18 326.9,19.18 327.02,19.3 327.02,23.11 326.77,23.11 326.77,20.45 326.64,20.32 324.74,20.32 324.61,20.45 324.61,23.11 324.23,23.11 324.23,19.43
3P3VSRC on TOP: 331.77,23.11 332.05,23.11 332.05,19.96 332.46,19.56 333.12,19.56 333.38,19.3 333.38,18.92 333.12,18.67 332.11,18.67 331.77,19
3P3VSRC on TOP: 331.77,3.02 332.03,3.02 332.03,5.77 332.49,6.22 332.99,6.22 333.25,6.48 333.25,6.71 332.99,6.96 330.96,6.96 330.71,6.71 330.71,6.48 330.96,6.22 331.22,6.22 331.77,5.66
3P3VSRC on TOP: 320.04,11.2 320.04,10.95 316.89,10.95 315.72,9.78 315.72,8.13 315.34,7.75 314.96,7.75 314.71,8 314.71,10.03 314.96,10.29 315.21,10.29 316.13,11.2
3P3VSRC on TOP: 337.95,12.45 337.95,12.7 334.77,12.7 334.64,12.83 334.14,12.83 334.01,12.7 334.01,10.54 334.24,10.31 334.54,10.31 334.77,10.54 334.77,11.94 335.28,12.45
3P3VSRC on BOTTOM: 316.61,10.29 314.71,10.29 314.71,7.75 316.61,7.75
3P3VSRC on BOTTOM: 333.25,5.08 333.25,6.99 330.71,6.99 330.71,5.08
3P3VSRC on BOTTOM: 335.92,12.83 334.01,12.83 334.01,10.29 335.92,10.29
3P3VSRC on BOTTOM: 324.23,21.08 324.23,19.18 326.77,19.18 326.77,21.08
3P3VSRC on L4_SIG: 177.04,27.69 177.04,19.18 157.1,19.18 157.1,27.69
3P3VSRC on L6_PWR: 339.85,4.19 339.85,16.38 333.38,16.38 333.38,12.83 334.77,12.83 334.77,6.22 330.45,6.22 330.45,9.78 331.22,9.78 331.22,16.38 330.45,16.38 330.45,20.57 326.77,20.57 326.77,19.05 319.02,19.05 319.02,7.75 310.01,7.75 310.01,14.22 254.25,14.22 254.25,16.38 247.65,16.38 247.65,14.22 233.17,14.22 233.17,15.11 201.93,15.11 201.93,14.22 160.27,14.22 160.27,19.05 152.4,19.05 152.4,27.56 174.62,27.56 174.62,25.78 176.91,25.78 176.91,27.56 405.13,27.56 405.13,8.89 395.1,8.89 395.1,4.19
5P0VSRC on TOP: 33.27,13.72 33.27,14.22 32.77,14.73 32.77,15.62 31.24,15.62 31.24,14.73 30.73,14.22 30.73,13.72
5P0VSRC on TOP: 113.79,10.67 113.79,11.18 113.28,11.68 113.28,12.57 111.76,12.57 111.76,11.68 111.25,11.18 111.25,10.67
5P0VSRC on TOP: 78.74,9.02 78.74,9.53 78.23,10.03 78.23,10.92 76.71,10.92 76.71,10.03 76.2,9.53 76.2,9.02
5P0VSRC on TOP: 54.86,13.59 54.86,11.05 54.36,11.05 53.85,11.56 52.96,11.56 52.96,13.08 53.85,13.08 54.36,13.59
5P0VSRC on TOP: 83.44,17.02 83.44,17.53 85.98,17.53 85.98,17.02 85.47,16.51 85.47,15.62 83.95,15.62 83.95,16.51
5P0VSRC on TOP: 129.29,22.99 129.29,23.5 128.91,23.88 128.91,24.89 127.13,24.89 127.13,23.88 126.75,23.5 126.75,22.99
5P0VSRC on TOP: 244.09,5.08 244.09,4.06 244.35,3.81 244.35,3.17 242.32,3.17 242.32,3.68 242.57,3.94 242.57,5.08
5P0VSRC on TOP: 33.27,22.86 33.27,23.37 32.77,23.88 32.77,24.77 31.24,24.77 31.24,23.88 30.73,23.37 30.73,22.86
5P0VSRC on TOP: 33.27,4.57 33.27,5.08 32.77,5.59 32.77,6.48 31.24,6.48 31.24,5.59 30.73,5.08 30.73,4.57
5P0VSRC on TOP: 238.89,9.14 237.87,9.14 237.62,8.89 236.98,8.89 236.98,10.92 237.49,10.92 237.74,10.67 238.89,10.67
5P0VSRC on TOP: 238.89,15.49 237.87,15.49 237.62,15.24 236.98,15.24 236.98,17.27 237.49,17.27 237.74,17.02 238.89,17.02
5P0VSRC on TOP: 242.57,21.08 242.57,22.23 242.32,22.48 242.32,23.11 244.35,23.11 244.35,22.61 244.09,22.35 244.09,21.08
5P0VSRC on L4_SIG: 190.25,17.14 190.25,22.1 194.69,22.1 194.69,27.69 244.6,27.69 244.6,19.56 233.68,19.56 233.68,17.14
5P0VSRC on L4_SIG: 222.25,16.51 222.25,10.03 233.55,10.03 233.55,7.24 244.6,7.24 244.6,2.54 201.29,2.54 201.29,16.51
5P0VSRC on L4_SIG: 222.88,16.51 222.88,10.67 234.19,10.67 234.19,7.87 239.52,7.87 239.52,18.92 234.31,18.92 234.31,16.51
5P0VSRC on L5_SIG: 233.04,15.62 233.04,11.18 179.83,11.18 179.83,4.83 138.18,4.83 138.18,27.69 161.29,27.69 161.29,14.73 156.21,14.73 156.21,10.54 172.85,10.54 172.85,18.8 187.96,18.8 187.96,20.19 200.53,20.19 205.1,15.62
5P0VSRC on L6_PWR: 1.27,27.56 1.27,1.27 41.4,1.27 41.4,8.89 99.82,8.89 99.82,14.22 111.25,14.22 111.25,6.99 116.97,6.99 116.97,14.22 159.64,14.22 159.64,18.41 151.76,18.41 151.76,27.56
AD_1P8VSRC on TOP: 262.25,14.99 262.25,13.46 263.4,13.46 263.65,13.21 264.16,13.21 264.16,15.24 263.65,15.24 263.4,14.99
AD_1P8VSRC on L3_PWR: 157.23,1.27 157.23,5.33 176.4,5.33 176.4,10.16 205.36,10.16 205.36,8.38 265.18,8.38 265.18,15.62 262.89,15.62 262.89,17.91 273.18,17.91 273.18,1.27
AD_1P8VSRC on L4_SIG: 177.67,27.69 177.67,18.54 157.1,18.54 157.1,2.54 184.4,2.54 184.4,27.69
AD_1P8VSRC on L4_SIG: 272.42,17.91 272.42,13.08 262.51,13.08 262.51,17.91
AD_3P3VSRC on TOP: 263.65,12.32 264.16,12.32 264.16,10.29 263.65,10.29 263.4,10.54 262.25,10.54 262.25,12.06 263.4,12.06
AD_3P3VSRC on TOP: 114.55,17.78 114.55,19.94 113.03,19.94 113.03,17.78
AD_3P3VSRC on TOP: 57.15,18.03 57.15,18.54 56.64,19.05 56.64,19.94 55.12,19.94 55.12,19.05 54.61,18.54 54.61,18.03
AD_3P3VSRC on TOP: 96.77,18.03 96.77,18.54 96.27,19.05 96.27,19.94 94.74,19.94 94.74,19.05 94.23,18.54 94.23,18.03
AD_3P3VSRC on BOTTOM: 200.66,22.1 200.66,24 199.14,24 199.14,22.1
AD_3P3VSRC on BOTTOM: 231.14,22.1 231.14,24 229.62,24 229.62,22.1
AD_3P3VSRC on L3_PWR: 273.81,1.27 273.81,18.54 262.25,18.54 262.25,16.38 247.78,16.38 247.78,19.56 113.92,19.56 113.92,16.89 71.37,16.89 71.37,18.92 68.58,18.92 68.58,16.89 29.21,16.89 29.21,27.56 156.84,27.56 156.84,25.91 190.25,25.91 190.25,27.56 286.51,27.56 286.51,1.27
AD_3P3VSRC on L4_SIG: 283.59,5.71 283.59,12.45 262.51,12.45 262.51,6.99 265.18,6.99 266.45,5.71
AD_3P3VSRC on L5_SIG: 187.32,19.43 187.32,27.69 181.74,27.69 181.74,19.43
AD_VCOM on L6_PWR: 106.05,1.27 106.05,8.89 100.46,8.89 100.46,13.59 110.62,13.59 110.62,1.27
AMP_VCOM_CH5_P02 on TOP: 47.5,19.18 47.5,16.89 46.74,16.89 46.74,19.18
AMP_VCOM_CH5_P02 on L5_SIG: 50.16,5.71 50.16,19.43 41.53,19.43 41.53,2.16 45.34,2.16 45.34,5.71
AMP_VCOM_CH8_P03 on TOP: 87.12,19.18 87.12,16.89 86.36,16.89 86.36,19.18
AMP_VCOM_CH8_P03 on L5_SIG: 63.5,2.29 63.5,13.08 85.6,13.08 85.6,19.18 90.81,19.18 90.81,5.21 67.44,5.21 67.44,2.29
INT_2P5VREF_P02 on L6_PWR: 119.51,13.59 119.51,5.33 129.03,5.33 129.03,1.27 133.48,1.27 133.48,13.59
N66709_P04 on BOTTOM: 244.35,12.95 244.35,10.79 244.86,10.79 245.36,11.3 246.25,11.3 246.25,12.95
N66709_P04 on L3_PWR: 116.46,6.1 116.46,1.27 156.59,1.27 156.59,5.97 175.77,5.97 175.77,10.79 205.99,10.79 205.99,9.02 247.14,9.02 247.14,13.34 242.06,13.34 242.06,12.06 209.17,12.06 209.17,14.1 163.32,14.1 163.32,12.45 148.72,12.45 148.72,5.59 125.48,5.59 125.48,9.91 100.84,9.91 100.84,6.1
Net_5 on TOP (solid shape): 46.35,19.56 42.93,19.56 42.93,22.61 46.35,22.61
SRC_EXT_VCOM_P03 on BOTTOM: 98.3,2.03 98.3,4.7 95.63,4.7 95.63,2.03
SRC_EXT_VCOM_P03 on L6_PWR: 97.16,4.57 97.16,1.27 70.1,1.27 70.1,4.57
TRIMER_P02 on TOP: 121.08,15.88 121.08,20.5 122.05,21.46 122.05,22.48 119.38,22.48 119.38,21.59 120.47,20.5 120.47,15.88
TRIMER_P02 on L4_SIG: 122.05,6.86 122.05,22.48 116.71,22.48 116.71,6.86
VCOM on BOTTOM (solid shape): 50.55,2.29 48.26,2.29 48.26,5.33 50.55,5.33
VCOM on BOTTOM (solid shape): 59.69,2.29 57.4,2.29 57.4,5.33 59.69,5.33
VCOM on BOTTOM: 100.58,4.7 100.58,2.79 101.09,2.79 101.09,2.03 98.81,2.03 98.81,2.79 99.31,2.79 99.31,4.7
VCOM on L6_PWR: 42.04,1.27 42.04,8.26 105.41,8.26 105.41,1.27 97.79,1.27 97.79,5.21 69.47,5.21 69.47,1.27
VREF on TOP (solid shape): 128.78,8.13 128.27,7.62 128.27,6.73 126.75,6.73 126.75,7.62 126.24,8.13 126.24,8.64 128.78,8.64
VREF on TOP: 54.86,9.78 54.86,7.24 54.36,7.24 53.85,7.75 52.96,7.75 52.96,9.27 53.85,9.27 54.36,9.78
VREF on TOP: 247.14,18.8 247.14,16.76 246.89,16.51 245.75,16.51 245.75,19.05 246.89,19.05
VREF on TOP: 238.89,13.97 238.89,12.45 237.74,12.45 237.49,12.19 236.98,12.19 236.98,14.22 237.49,14.22 237.74,13.97
VREF on BOTTOM: 238.12,14.22 238.12,12.06 236.98,12.06 236.98,14.22
VREF on BOTTOM: 246.51,16.51 247.14,16.51 247.14,19.05 246.51,19.05 246,18.54 245.24,18.54 245.24,17.02 246,17.02
VREF on L3_PWR: 6.1,27.56 6.1,13.72 12.57,7.24 96.14,7.24 96.14,2.92 103.12,2.92 103.12,5.46 100.2,5.46 100.2,10.54 126.11,10.54 126.11,6.35 148.08,6.35 148.08,13.08 162.69,13.08 162.69,14.73 209.8,14.73 209.8,12.7 241.43,12.7 241.43,13.97 247.14,13.97 247.14,18.92 114.55,18.92 114.55,16.26 70.74,16.26 70.74,18.29 69.22,18.29 69.22,16.26 28.57,16.26 28.57,27.56
VREF on L4_SIG: 126.24,8.64 126.24,6.73 128.65,6.73 129.29,6.1 129.29,3.56 129.79,3.05 130.3,3.05 130.81,3.56 130.81,6.1 131.06,6.35 132.59,6.35 132.84,6.6 132.84,9.53 129.29,9.53 129.29,8.64
XT_VOUT_P02 on L6_PWR: 128.4,1.27 128.4,4.7 119.51,4.7 119.51,1.27

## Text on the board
BOTTOM: LAYER 8 - BOTTOM SIDE | 8
Ref Des/Assembly Bottom: ASSEMBLY DRAWING - BOTTOM SIDE | 12
Package Geometry/Pastemask Bottom: SOLDER PASTE - BOTTOM SIDE | 10
TOP: JP3 | U2 | U1 | U3 | JP4 | U7 | JP9 | U8 | JP8 | JP502 | U9 | U10 | U11 | JP26 | U12 | U14 | JP500 | U5 | U13 | JP6 | U6 | JP5 | JP2 | JP12 | JP11 | TP10 | TP8 | TP12 | TP11 | U4 | JP13 | TP5 | JP7 | JP10 | JP16 | JP15 | TP6 | JP1 | JP14 | U19 | JP21 | JP20 | JP19 | JP27 | JP18 | U18 | JP17 | U15 | JP23 | U16 | U17 | JP22 | TP9 | TP1 | TP2 | TP3 | TP4 | TP7 | LAYER 1 - TOP SIDE | 1 | HEATEVM REV B | 6526561
Ref Des/Assembly Top: * | ASSEMBLY DRAWING - TOP SIDE | 11
Package Geometry/Pastemask Top: SOLDER PASTE - TOP SIDE | 9
L2_GND: LAYER 2 - GROUND | 2
L3_PWR: LAYER 3 - POWER | 3
L4_SIG: LAYER 4 - SIGNAL | 4
L5_SIG: LAYER 5 - SIGNAL | 5
L6_PWR: LAYER 6 - POWER | 6
L7_GND: LAYER 7 - GROUND | 7
DIMENSION: FABRICATION DRAWING | 13
User.16: AND MEET OR EXCEED IPC-4552.  2 uIN MIN OF IMMERSION GOLD APPLIED OVER | FABRICATION NOTES: | BEST INDUSTRY PRACTICE IPC-A-600C (COMMERCIAL STANDARD). | PROCESS NOTES: | TRACE WIDTHS AND ROUTING: | 1: COPPER PLATING TO BE 0.001 INCH MINIMUM IN ALL PLATED THROUGH HOLES. | 2: CIRCUITRY ON OUTER LAYERS TO BE ELECTROLESS NICKEL IMMERSION GOLD | 1: ALL FABRICATION ITEMS MUST MEET OR EXCEED | 2: LAMINATE MATERIAL: POLYIMIDE. | 3: COPPER WEIGHT: 1.0 OZ MIN OUTER LAYERS / 1.0 OZ INNER LAYERS. | 4: FINISH BOARD THICKNESS: 0.106 +/- 0.007 INCH. | 5: POSITION ACCURACY: +/- .0015 INCH. | 6: WARP AND TWIST NOT TO EXCEED .020/ INCH. | 7: CONTROLLED IMPEDANCE LAYERS: TOP & BOTTOM | 8: LAYER COUNT: 8. | 9: VIA PADS FOR ALL UNUSED INTERNAL SIGNAL LAYERS MAY BE REMOVED DURING | BOARD MANUFACTURING. | 3: SOLDERMASK : NONE. | 4: SILKSCREEN: NONE. | 5: THIS BOARD MUST BE RoHS COMPLIANT. | 6: 1.2mil PLATING ON ALL PLATED THROUGH HOLES MINIMUM. | SAMPLE CROSS SECTION MUST BE PROVIDED BY VENDOR. | 1: TRACE WIDTH CALCULATIONS ARE STARTING VALUES. BOARD SHOP MAY | ADJUST TRACE WIDTHS TO COMPENSATE FOR PROCESS. | 2: DIELECTRIC CONSTANT:POLYIMIDE. | 3: LAYER 1 AND 8 HAVE 50OHM +/- 10% SINGLE ENDED USING AN 14.25mil TRACE. | 2: LAYER 1 AND 8 HAVE 100OHM +/- 10% DIFFERENTIAL PAIR USING AN 7.0mil TRACE | AND 4.0mil SPACING.
User.28: CUSTOMER: | BOARD NAME: | Engineer: | PCB Dsgnr: | LAYER DESCRIPTION: | BOARD REV: | KS ID: | RELEASE DATE: | JOB NUMBER: | SHEET NUMBER: | TEXAS INSTRUMENTS | HEATEVM | APR-21-2012 | 13 | HECTOR TORRES | NIMA KARI | B | 12914 | of | 117059
User.30: FIGURE | SIZE | 14.0 | 30.0 | 38.0 | 70.0 | 125.0 | DRILL CHART: TOP to BOTTOM | ALL UNITS ARE IN MILS | TOLERANCE | +3.0/-3.0 | PLATED | QTY | 606 | 58 | 188 | 2 | 10
